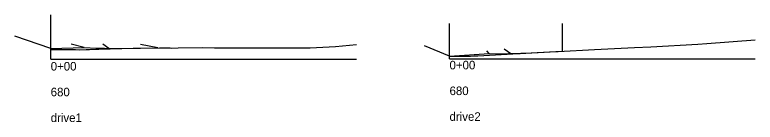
# Model space of a CAD drawing. Extents: x 157201 to 163282, y 424960 to 427200.
# Drawn here: x 162438.8 to 162681, y 425259.7 to 425294.7 of the extents above; entities that cross this region are included whole.
import ezdxf

# ---------------------------------------------------------------- set-up
doc = ezdxf.new("R2010")
doc.units = 0
for name, color, linetype in [('Default', 7, 'Continuous'), ('RD_X_Concrete_Pad', 7, 'Continuous'), ('UT_X_Water_Cells', 7, 'Continuous')]:
    doc.layers.add(name, color=color, linetype=linetype)

msp = doc.modelspace()

# ---------------------------------------------------------------- linework, layer by layer
at = {"layer": 'Default'}
for p, q in [((162450.54, 425280.26), (162450.54, 425294.73)), ((162581.03, 425280.41), (162581.03, 425291.91)), ((162618.03, 425282.88), (162618.03, 425291.91)), ((162450.54, 425283.69), (162438.8, 425287.78)), ((162461.54, 425284.03), (162457.29, 425285.2)), ((162469.54, 425283.72), (162467.61, 425285.21)), ((162485.54, 425283.93), (162479.94, 425285.1)), ((162581.03, 425281.21), (162572.87, 425284.56)), ((162594.03, 425282.06), (162593.23, 425282.96)), ((162601.03, 425281.99), (162598.85, 425283.49)), ((162450.54, 425280.26), (162550.54, 425280.26)), ((162581.03, 425280.41), (162681.03, 425280.41))]:
    msp.add_line(p, q, dxfattribs=at)
at = {"layer": 'RD_X_Concrete_Pad'}
for p, q in [((162450.54, 425283.69), (162461.54, 425284.03)), ((162461.54, 425284.03), (162465.54, 425283.88)), ((162473.54, 425283.77), (162485.54, 425283.93)), ((162581.03, 425281.21), (162594.03, 425282.06)), ((162594.03, 425282.06), (162596.03, 425282.04)), ((162606.03, 425282.25), (162618.03, 425282.88))]:
    msp.add_line(p, q, dxfattribs=at)
for points in [[(162465.54, 425283.88), (162469.54, 425283.72), (162473.54, 425283.77)], [(162596.03, 425282.04), (162601.03, 425281.99), (162606.03, 425282.25)]]:
    msp.add_open_spline(points, degree=2, dxfattribs=at)
at = {"layer": 'UT_X_Water_Cells'}
for points in [[(162450.54, 425283.46), (162458.61, 425283.39), (162459.99, 425283.34), (162462.16, 425283.41), (162462.36, 425283.43), (162462.51, 425283.41), (162462.58, 425283.42), (162462.89, 425283.42), (162463.2, 425283.44), (162465.3, 425283.51), (162466.26, 425283.52), (162477.56, 425283.8), (162478.57, 425283.82), (162479.87, 425283.86), (162486.1, 425283.93), (162489.62, 425283.92), (162490.03, 425283.89), (162492.27, 425283.94), (162500.18, 425284.1), (162504.17, 425283.93), (162505.43, 425283.93), (162510.47, 425283.93), (162516.56, 425283.97), (162517.69, 425283.95), (162523.59, 425283.91), (162535.41, 425283.96), (162543.68, 425284.38), (162543.75, 425284.37), (162550.54, 425285.06)], [(162581.03, 425281.23), (162584.84, 425281.2), (162586.38, 425281.22), (162587.02, 425281.23), (162587.9, 425281.24), (162589.04, 425281.33), (162589.2, 425281.34), (162589.27, 425281.34), (162589.45, 425281.35), (162589.69, 425281.36), (162590, 425281.37), (162590.34, 425281.39), (162603.68, 425282.09), (162603.73, 425282.1), (162603.8, 425282.1), (162603.93, 425282.11), (162609.72, 425282.43), (162615.82, 425282.77), (162616.03, 425282.78), (162616.55, 425282.81), (162628.44, 425283.4), (162641.53, 425284.05), (162646.85, 425284.33), (162662.27, 425285.12), (162665.26, 425285.34), (162681.03, 425286.57)]]:
    msp.add_lwpolyline(points, dxfattribs=at)

# ---------------------------------------------------------------- texts
at = {"layer": 'Default'}
for s, p in [('0+00', (162581.03, 425276.93)), ('0+00', (162450.54, 425276.54)), ('680', (162450.54, 425268.14)), ('680', (162581.03, 425268.53)), ('drive1', (162450.54, 425259.74)), ('drive2', (162581.03, 425260.13))]:
    msp.add_text(s, height=2.8, dxfattribs=at).set_placement(p)

doc.saveas('drawing.dxf')
